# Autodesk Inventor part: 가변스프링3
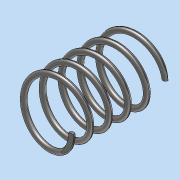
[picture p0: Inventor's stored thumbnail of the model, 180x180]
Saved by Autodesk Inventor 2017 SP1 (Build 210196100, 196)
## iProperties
Part Number: 가변스프링3
Material: 강철, 연강
Document SubType Name: Modeling
Designer: MRC
Density: 7.85 g/cm^3
Appearance: 반연마
Mass: 8.42324 g
Surface Area: 21.7217 cm^2
Volume: 1.07302 cm^3
Author: MRC
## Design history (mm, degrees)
sketch "스케치1"
  geometry: L1 (0, 0)-(0, 36.411); L2 (0, 36.411)-(11, 36.411); L3 (0, 0)-(11, 0); C1 r 1 at (11, 0)
  constraints: 6 end point, 2 horizontal, 1 centre point, 1 coincident, 1 vertical
  dimensions: "d0" = 36.4112 distance of L1.start L1.end (derived); "d1" = 11 distance of L1.end L2.end; "d2" = 22 diameter of L3.end L1; "d3" = 2 diameter of C1
feature "코일1" sketch "스케치1" pitch "d4" = 10; turns "d6" = 5; dims "d5" = 36.4112 (= d0), "d7" = 0, angle "d8" = 90 deg, angle "d9" = 90 deg, "d10" = 0, "d11" = 0
sketch "스케치2"
  geometry: L1 (36.411, 20)-(0, 20); L2 (0, 20)-(0, -20); L3 (0, -20)-(36.411, -20); L4 (36.411, -20)-(36.411, 20); 2 further points
  constraints: 8 end point, 2 parallel, 1 coincident, 1 horizontal, 1 midpoint, 1 perpendicular
  dimensions: "d12" = 36.4112 distance of L2.end L3.end (= d0); "d13" = 40 distance of L3.end L1.start
extrude "돌출1" sketch "스케치2" stored distance "d14" = 0; taper "d15" = 0 deg
node "솔리드1"
